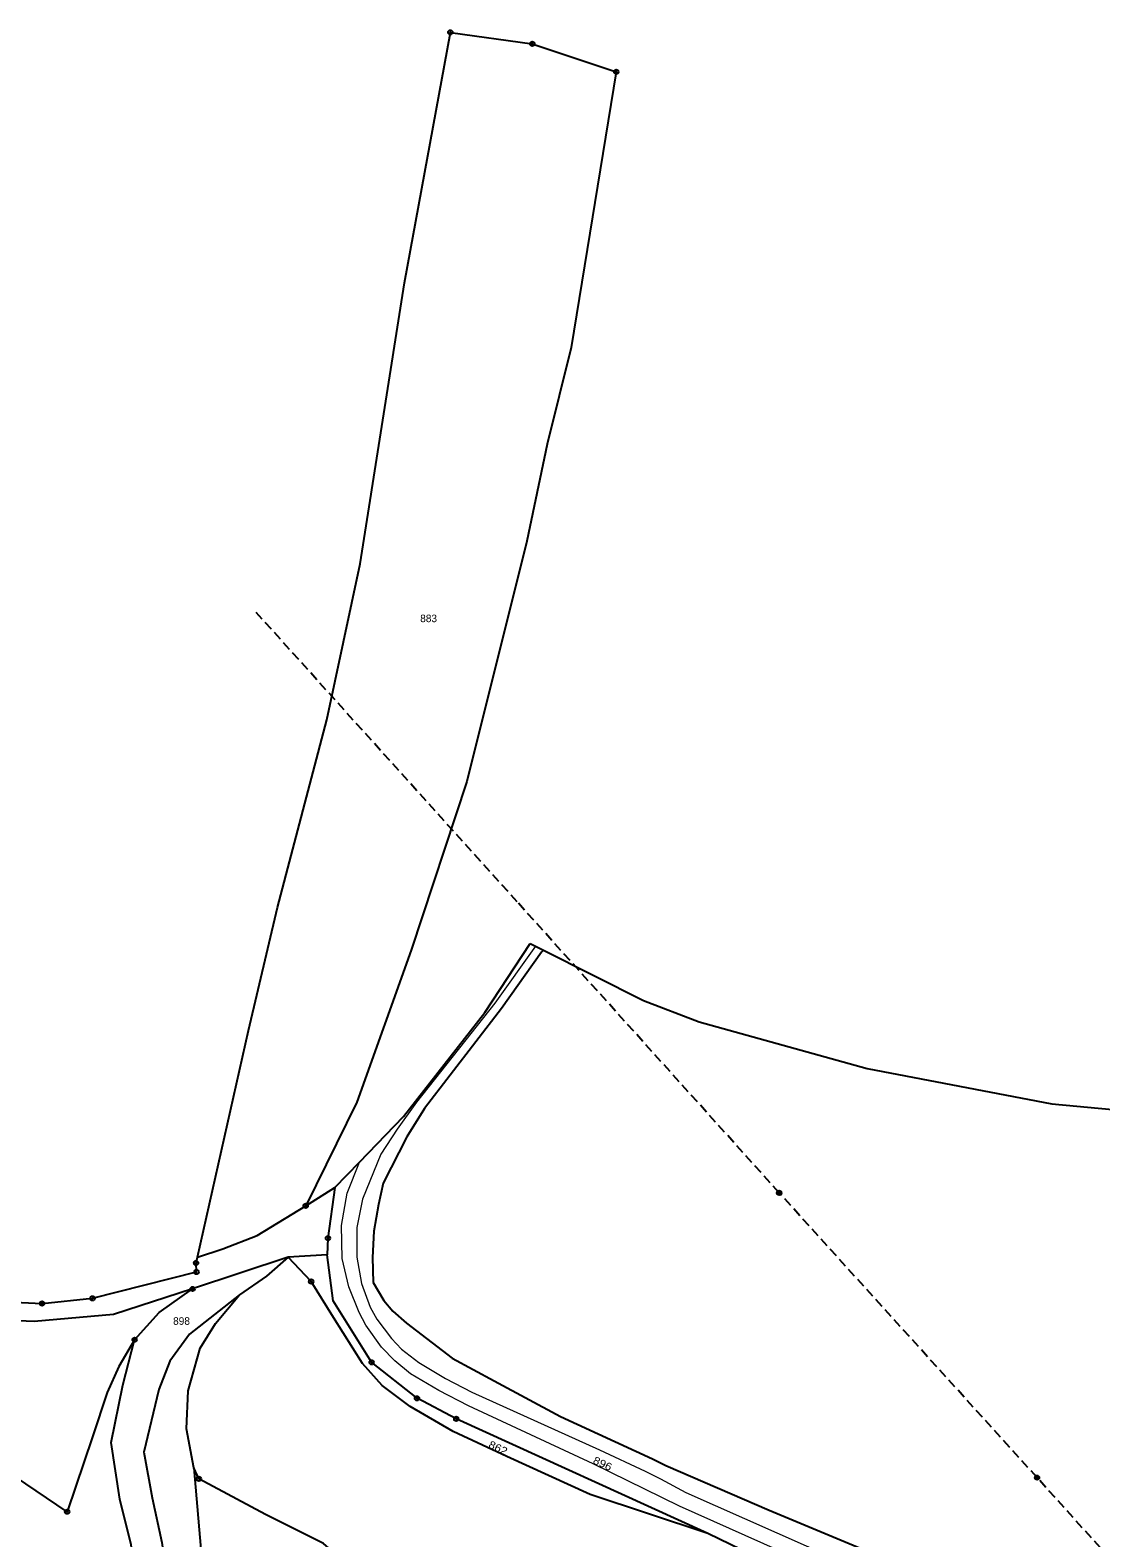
# Model space of a CAD drawing. Extents: x -754445 to -751443, y -1030748 to -1028224.
# Drawn here: x -753984.8 to -753743.7, y -1028563 to -1028223.6 of the extents above; entities that cross this region are included whole.
import ezdxf
from ezdxf.enums import TextEntityAlignment as Align

# ---------------------------------------------------------------- set-up
doc = ezdxf.new("R2010")
doc.units = 0
doc.header["$LTSCALE"] = 0.68
doc.linetypes.add('MEDIUM_DASHED', pattern=[4.5, 3, -1.5])
for name, color, linetype, lineweight in [('1', 7, 'Continuous', 25), ('4', 7, 'Continuous', 13), ('6', 7, 'Continuous', 25), ('8', 7, 'Continuous', 25)]:
    doc.layers.add(name, color=color, linetype=linetype, lineweight=lineweight)
doc.layers.add('2', color=7, linetype='Continuous')

msp = doc.modelspace()

# ---------------------------------------------------------------- linework, layer by layer
at = {"layer": '1'}
msp.add_line((-753926.75, -1028499.84), (-753948.24, -1028506.97), dxfattribs=at)
for points in [[(-753947.15, -1028499.8), (-753935.63, -1028448.76), (-753929.12, -1028421.06), (-753918.02, -1028378.88), (-753910.49, -1028343.72), (-753900.54, -1028280.49), (-753890.19, -1028224.07)], [(-753890.19, -1028224.07), (-753871.74, -1028226.65), (-753852.83, -1028232.95)], [(-753852.83, -1028232.95), (-753863.02, -1028295.01), (-753868.38, -1028316.8), (-753872.97, -1028338.62), (-753886.5, -1028392.73), (-753899.01, -1028430.7), (-753911.26, -1028464.93), (-753922.77, -1028488.27)], [(-753910.66, -1028478.43), (-753900.74, -1028468.13), (-753882.41, -1028444.71), (-753872.24, -1028429.22)], [(-753872.24, -1028429.22), (-753871.03, -1028429.83), (-753869.25, -1028430.72)], [(-753869.25, -1028430.72), (-753869.64, -1028431.12), (-753878.69, -1028443.8), (-753896, -1028466.35), (-753899.96, -1028472.71), (-753905.29, -1028483.16), (-753906.36, -1028487.97), (-753907.41, -1028493.96), (-753907.75, -1028499.93), (-753907.55, -1028505.56), (-753905.14, -1028509.58), (-753903.15, -1028512.01), (-753900.06, -1028514.69), (-753889.75, -1028522.56), (-753880.32, -1028527.66), (-753865.36, -1028535.68), (-753844.67, -1028545.19), (-753841.66, -1028546.73), (-753818.43, -1028556.78), (-753796.76, -1028565.81)], [(-753869.25, -1028430.72), (-753846.73, -1028442.02), (-753834.15, -1028446.82), (-753796.32, -1028457.35), (-753754.76, -1028465.3), (-753687.24, -1028471.61), (-753629.81, -1028476.88)], [(-753922.77, -1028488.27), (-753916.17, -1028484.16), (-753910.66, -1028478.43)], [(-753916.17, -1028484.16), (-753917.76, -1028495.54), (-753917.92, -1028499.29)], [(-754377.46, -1028522.03), (-754358.71, -1028521.23), (-754325.11, -1028516.04), (-754312.19, -1028513.72), (-754281.72, -1028507), (-754251.56, -1028501.34), (-754231.39, -1028498.15), (-754176.29, -1028491.34), (-754158.58, -1028490.31), (-754128.79, -1028489.96), (-754089.82, -1028493.19), (-754058.44, -1028499.31), (-754032.41, -1028505.8), (-754008.62, -1028508.97), (-753982.13, -1028510.26), (-753970.76, -1028509.09), (-753947.34, -1028503.16)], [(-753947.15, -1028499.8), (-753941.41, -1028497.97), (-753933.68, -1028494.98), (-753922.77, -1028488.27)], [(-753947.34, -1028503.16), (-753947.45, -1028501.14), (-753947.15, -1028499.8)], [(-753926.75, -1028499.84), (-753931.59, -1028504.07), (-753937.68, -1028508.28)], [(-753832.22, -1028562.02), (-753888.87, -1028536.22), (-753897.7, -1028531.6), (-753907.93, -1028523.49), (-753916.55, -1028509.64), (-753917.92, -1028499.29), (-753926.75, -1028499.84)], [(-753832.22, -1028562.02), (-753858.7, -1028553.25), (-753877.49, -1028544.71), (-753889.59, -1028539.05), (-753899.22, -1028533.45), (-753905.53, -1028528.74), (-753909.94, -1028523.77), (-753916.54, -1028513.44), (-753921.54, -1028505.31), (-753926.75, -1028499.84)], [(-753961.29, -1028518.41), (-753964.86, -1028524.46), (-753967.46, -1028530.29), (-753970.79, -1028540.27), (-753976.48, -1028557.14), (-753988.09, -1028549.29), (-754014.02, -1028533.42), (-754026.78, -1028526.58), (-754057.05, -1028505.58)], [(-753948.24, -1028506.97), (-753966.07, -1028512.7), (-753983.93, -1028514.3), (-754007.65, -1028513.36), (-754057.05, -1028505.58)], [(-753937.68, -1028508.28), (-753948.95, -1028517.15), (-753953.36, -1028523.25), (-753955.83, -1028529.6), (-753959.25, -1028543.73), (-753957.36, -1028553.97), (-753955.13, -1028564.04), (-753954.06, -1028572.12), (-753955.21, -1028577.4), (-753959.25, -1028582.18), (-753965.94, -1028584.66), (-753974.27, -1028586.14), (-753978.87, -1028590.59), (-753979.24, -1028594.23), (-753976.63, -1028610.39), (-753974.42, -1028624.38), (-753970.16, -1028636.62), (-753966.61, -1028640.47)], [(-753961.29, -1028518.41), (-753955.79, -1028512.31), (-753948.24, -1028506.97)], [(-753947.94, -1028547.26), (-753949.62, -1028538.49), (-753949.25, -1028529.94), (-753946.56, -1028520.34), (-753943.07, -1028514.72), (-753937.68, -1028508.28)], [(-753982.35, -1028606.7), (-753984.14, -1028594.54), (-753984.26, -1028590.84), (-753983.83, -1028587.59), (-753983.2, -1028585.59), (-753981.63, -1028583.39), (-753975.6, -1028579.35), (-753968.5, -1028577.81), (-753962.64, -1028574.84), (-753961.23, -1028570.06), (-753962.06, -1028564.61), (-753964.62, -1028554.3), (-753966.55, -1028541.52), (-753963.92, -1028528.66), (-753961.29, -1028518.41)], [(-753757.86, -1028624.79), (-753768.78, -1028623.93), (-753790.82, -1028622.87), (-753804.27, -1028622.52), (-753822.85, -1028620.1), (-753848.19, -1028614.39), (-753858.06, -1028610.35), (-753864.41, -1028606.2), (-753874.22, -1028598.34), (-753897.57, -1028582.87), (-753918.75, -1028564.3), (-753931.84, -1028557.78), (-753946.83, -1028549.73), (-753947.94, -1028547.26), (-753941.11, -1028626.59)], [(-753789.48, -1028583.58), (-753799.74, -1028577.76), (-753832.22, -1028562.02)]]:
    msp.add_lwpolyline(points, dxfattribs=at)
at = {"layer": '4'}
for points in [[(-753871.03, -1028429.83), (-753880.18, -1028442.64), (-753897.81, -1028464.91), (-753902.15, -1028470.99), (-753905.81, -1028476.63), (-753909.96, -1028486.73), (-753911.28, -1028493.13), (-753911.23, -1028499.8), (-753910.21, -1028505.76), (-753908.24, -1028511.07), (-753906.76, -1028513.75), (-753903.42, -1028518.13), (-753901.19, -1028520.53), (-753897.29, -1028523.55), (-753891.29, -1028527.16), (-753885.37, -1028530.25), (-753856.64, -1028543.21), (-753846.33, -1028547.98), (-753842.85, -1028549.76), (-753837.16, -1028552.8), (-753803.48, -1028567.75)], [(-753804.84, -1028570.93), (-753838.56, -1028555.86), (-753858.06, -1028546.34), (-753886.12, -1028533.31), (-753892.81, -1028529.87), (-753899.14, -1028526.11), (-753902.7, -1028523.15), (-753905.66, -1028520.06), (-753909.21, -1028515.15), (-753910.76, -1028512.31), (-753913.03, -1028506.51), (-753914.53, -1028500.14), (-753914.72, -1028492.67), (-753913.44, -1028485.45), (-753910.66, -1028478.43)]]:
    msp.add_lwpolyline(points, dxfattribs=at)
at = {"layer": '6', "linetype": 'MEDIUM_DASHED'}
msp.add_lwpolyline([(-753499.83, -1028865.29), (-753527.61, -1028823.3), (-753570.95, -1028756.74), (-753608.62, -1028714.93), (-753648.01, -1028671.11), (-753702.8, -1028610.73), (-753758.07, -1028549.45), (-753816.14, -1028485.34), (-753875.16, -1028419.8), (-753934.32, -1028354.21)], dxfattribs=at)
at = {"layer": '6'}
for centre, radius in [((-753816.1434, -1028485.3399), 0.5), ((-753816.1434, -1028485.3399), 0.4), ((-753816.1434, -1028485.3399), 0.3), ((-753816.1434, -1028485.3399), 0.2), ((-753816.1434, -1028485.3399), 0.1), ((-753758.0734, -1028549.4499), 0.5), ((-753758.0734, -1028549.4499), 0.4), ((-753758.0734, -1028549.4499), 0.3), ((-753758.0734, -1028549.4499), 0.2), ((-753758.0734, -1028549.4499), 0.1)]:
    msp.add_circle(centre, radius, dxfattribs=at)
at = {"layer": '8'}
for centre, radius in [((-753890.19, -1028224.0699), 0.5), ((-753890.19, -1028224.0699), 0.0303), ((-753871.74, -1028226.6499), 0.5), ((-753871.74, -1028226.6499), 0.0303), ((-753852.83, -1028232.9499), 0.5), ((-753852.83, -1028232.9499), 0.0303), ((-753922.77, -1028488.2699), 0.5), ((-753922.77, -1028488.2699), 0.0303), ((-753917.76, -1028495.5399), 0.5), ((-753917.76, -1028495.5399), 0.0303), ((-753947.45, -1028501.1399), 0.5), ((-753947.45, -1028501.1399), 0.0303), ((-753947.34, -1028503.1599), 0.5), ((-753947.34, -1028503.1599), 0.0303), ((-753921.54, -1028505.3099), 0.5), ((-753948.24, -1028506.9699), 0.5), ((-753948.24, -1028506.9699), 0.0303), ((-753921.54, -1028505.3099), 0.0303), ((-753982.13, -1028510.2599), 0.5), ((-753982.13, -1028510.2599), 0.0303), ((-753970.76, -1028509.0899), 0.5), ((-753970.76, -1028509.0899), 0.0303), ((-753961.29, -1028518.4099), 0.5), ((-753961.29, -1028518.4099), 0.0303), ((-753907.93, -1028523.4899), 0.5), ((-753907.93, -1028523.4899), 0.0303), ((-753897.7, -1028531.5999), 0.5), ((-753897.7, -1028531.5999), 0.0303), ((-753888.87, -1028536.2199), 0.5), ((-753888.87, -1028536.2199), 0.0303), ((-753946.83, -1028549.7299), 0.5), ((-753946.83, -1028549.7299), 0.0303), ((-753976.48, -1028557.1399), 0.5), ((-753976.48, -1028557.1399), 0.0303)]:
    msp.add_circle(centre, radius, dxfattribs=at)

# ---------------------------------------------------------------- texts
at = {"layer": '2'}
for s, p in [('883', (-753895.089, -1028356.856)), ('898', (-753950.729, -1028515.046))]:
    msp.add_text(s, height=1.7, dxfattribs=at).set_placement(p, align=Align.CENTER)
at = {"layer": '2', "width": 1.15}
for s, p in [('862', (-753879.7982, -1028543.5255)), ('896', (-753856.2582, -1028547.0755))]:
    msp.add_text(s, height=1.7, rotation=335, dxfattribs=at).set_placement(p, align=Align.CENTER)

doc.saveas('drawing.dxf')
